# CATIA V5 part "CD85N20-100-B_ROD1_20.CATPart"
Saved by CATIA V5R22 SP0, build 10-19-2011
Part number: CD85N20-100-B_ROD1_20
Revision: ANY
Definition: UNKNOWN
Nomenclature: CD85N20-100-B_ROD1_20
Source: Unknown
Bounding box of the stored display mesh (mm): x -10 to 10, y -10 to 10, z 0 to 177.5
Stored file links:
  U:\S9A\PER\CAO\Assemblage\Reservoir_Flacon\Verin\Poussoir_2\CD85N20-100-B_ROD1_20.CATPart
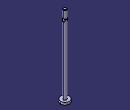
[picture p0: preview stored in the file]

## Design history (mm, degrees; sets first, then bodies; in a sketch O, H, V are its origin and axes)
Body1 "MALE_FLATS" (main body)
  Solid1: solid without history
